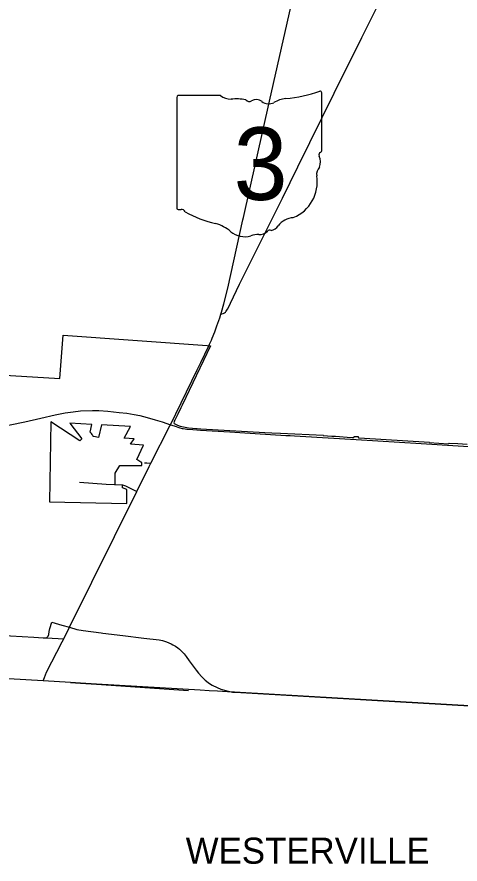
# Model space of a CAD drawing. Extents: x 1729596 to 1925846, y 659247 to 911751.
# Drawn here: x 1847054 to 1855559, y 773819 to 790063 of the extents above; entities that cross this region are included whole.
import ezdxf

# ---------------------------------------------------------------- set-up
doc = ezdxf.new("R2010")
doc.units = 0
for name, color, linetype in [('GM_X_City_Street', 7, 'Continuous'), ('GM_X_Corporation', 7, 'Continuous'), ('GM_X_Corporation_Text', 7, 'Continuous'), ('GM_X_County', 7, 'Continuous'), ('GM_X_County_Road', 7, 'Continuous'), ('GM_X_State_Route', 7, 'Continuous'), ('GM_X_State_Shield', 7, 'Continuous'), ('GM_X_Township_Road', 7, 'Continuous')]:
    doc.layers.add(name, color=color, linetype=linetype)

msp = doc.modelspace()

# ---------------------------------------------------------------- linework, layer by layer
at = {"layer": 'GM_X_City_Street'}
for points in [[(1845750, 781984), (1846636, 782185), (1847206, 782302), (1847513, 782368), (1847786, 782434), (1847977, 782469), (1848131, 782490), (1848273, 782507), (1848502, 782514), (1848624, 782515), (1848801, 782501), (1849017, 782481), (1849162, 782462), (1849304, 782438), (1849411, 782418), (1849555, 782383), (1849710, 782340), (1849838, 782298), (1850003, 782242)], [(1850003, 782242), (1850074, 782221), (1850183, 782185), (1850228, 782173), (1850245, 782170), (1850281, 782163), (1850312, 782159), (1850325, 782158), (1850431, 782150), (1850574, 782141), (1851143, 782107), (1851335, 782095)], [(1851335, 782095), (1852214, 782040)], [(1852214, 782040), (1852297, 782035), (1852381, 782031), (1852490, 782023), (1853564, 781958), (1854813, 781882), (1856233, 781796), (1856759, 781767), (1857122, 781742)], [(1849499, 781514), (1849547, 781511), (1849624, 781505)], [(1849078, 781088), (1849139, 781069), (1849352, 780964)], [(1846702, 778207), (1847381, 778168), (1847556, 778157), (1847623, 778159), (1847653, 778187), (1847668, 778222), (1847673, 778281), (1847683, 778338), (1847722, 778457)], [(1847722, 778457), (1847915, 778403), (1848062, 778361)], [(1848062, 778361), (1848204, 778314), (1848323, 778297), (1848668, 778252), (1848705, 778248)], [(1848705, 778248), (1849085, 778201), (1849491, 778152), (1849783, 778117), (1849847, 778104), (1849922, 778081), (1850012, 778044), (1850046, 778026), (1850094, 777998), (1850140, 777966), (1850171, 777942), (1850219, 777897), (1850262, 777849), (1850300, 777796), (1850362, 777718), (1850435, 777616), (1850491, 777539), (1850536, 777481), (1850600, 777410), (1850669, 777346), (1850724, 777300), (1850767, 777270), (1850802, 777249), (1850896, 777202), (1850967, 777174), (1851065, 777144), (1851193, 777116), (1851228, 777114), (1851242, 777113)], [(1847623, 778159), (1847953, 778140)], [(1848085, 777300), (1848276, 777289), (1848580, 777271), (1850345, 777150)], [(1851242, 777113), (1853977, 776957), (1854746, 776908), (1855849, 776844), (1860837, 776510)]]:
    msp.add_lwpolyline(points, dxfattribs=at)
at = {"layer": 'GM_X_Corporation'}
msp.add_lwpolyline([(1845556, 783268), (1847880, 783128), (1847941, 783961), (1850704, 783760), (1850771, 783756), (1850223, 782617), (1850199, 782567), (1850139, 782444), (1850095, 782354), (1850085, 782333), (1850074, 782313), (1850069, 782299), (1850068, 782279), (1850071, 782269), (1850095, 782252), (1850134, 782235), (1850187, 782215), (1850218, 782207), (1850250, 782200), (1850345, 782187), (1850498, 782169), (1850510, 782168), (1850585, 782164), (1851810, 782096), (1851944, 782088), (1852113, 782080), (1852935, 782042), (1852934, 782037), (1853098, 782027), (1853168, 782023), (1853247, 782018), (1853247, 782016), (1853395, 782006), (1853479, 782000), (1853492, 781999), (1853509, 781998), (1853511, 781998), (1853514, 781999), (1853517, 782000), (1853519, 782001), (1853521, 782002), (1853522, 782003), (1853524, 782005), (1853526, 782007), (1853527, 782010), (1853528, 782013), (1853529, 782016), (1853529, 782020), (1853603, 782018), (1853603, 782011), (1853603, 782008), (1853604, 782004), (1853605, 782001), (1853607, 781999), (1853608, 781997), (1853610, 781995), (1853614, 781993), (1853615, 781992), (1853618, 781992), (1853621, 781991), (1854969, 781911), (1854968, 781901), (1855339, 781880), (1855340, 781890), (1855349, 781890), (1855515, 781881), (1855693, 781873)], dxfattribs=at)
msp.add_lwpolyline([(1847680, 780763), (1849165, 780736), (1849163, 781002), (1849082, 781034), (1849083, 781084), (1848937, 781088), (1848942, 781314), (1849029, 781462), (1849454, 781459), (1849454, 781517), (1849430, 781526), (1849356, 781577), (1849486, 781850), (1849232, 781869), (1849306, 781970), (1849115, 781988), (1849235, 782207), (1848677, 782244), (1848617, 782001), (1848528, 782020), (1848519, 782020), (1848515, 782021), (1848510, 782031), (1848500, 782057), (1848482, 782077), (1848469, 782087), (1848458, 782099), (1848494, 782247), (1848066, 782273), (1848300, 781976), (1848262, 781937), (1847707, 782296)], close=True, dxfattribs=at)
at = {"layer": 'GM_X_County'}
msp.add_lwpolyline([(1855849, 776844), (1854746, 776908), (1853977, 776957), (1851228, 777114), (1851193, 777116), (1850903, 777132), (1850744, 777141), (1850569, 777151), (1848580, 777271), (1848276, 777289), (1848085, 777300), (1847560, 777333), (1845449, 777453), (1843361, 777564), (1842358, 777614), (1840924, 777694), (1840611, 777712), (1840257, 777736), (1837085, 777931), (1837011, 777935), (1836973, 777937), (1836651, 777955), (1835956, 777979)], dxfattribs=at)
at = {"layer": 'GM_X_County_Road'}
for points in [[(1851209, 784694), (1851326, 784936), (1852148, 786590), (1852443, 787187), (1853141, 788601), (1853675, 789667), (1853798, 789914), (1853979, 790280), (1854272, 790859), (1854392, 791103), (1854649, 791581), (1855260, 792799), (1855898, 794041), (1856273, 794777), (1856673, 795566), (1856869, 795971), (1857028, 796294)], [(1850968, 784364), (1851009, 784379), (1851023, 784383), (1851040, 784392), (1851054, 784403), (1851062, 784412), (1851069, 784422), (1851092, 784460), (1851118, 784507), (1851150, 784573), (1851209, 784694)]]:
    msp.add_lwpolyline(points, dxfattribs=at)
at = {"layer": 'GM_X_State_Route'}
for points in [[(1851027, 784561), (1851027, 784562), (1851101, 784861), (1851390, 786171), (1851399, 786214), (1851899, 788445), (1852470, 790966), (1852613, 791609), (1852746, 792202), (1852871, 792760), (1853072, 793659), (1853214, 794287), (1853225, 794338)], [(1850785, 783867), (1850801, 783904), (1850850, 784024), (1850893, 784139), (1850946, 784292), (1850968, 784364), (1850980, 784401), (1851027, 784561)], [(1850584, 783434), (1850737, 783758), (1850741, 783767), (1850750, 783788), (1850785, 783867)], [(1850003, 782242), (1850516, 783296), (1850578, 783422), (1850584, 783434)], [(1849593, 781442), (1849619, 781493), (1849624, 781505), (1849991, 782220), (1850003, 782242)], [(1847923, 778082), (1847953, 778140), (1848062, 778361), (1849352, 780964), (1849593, 781442)], [(1847560, 777333), (1847581, 777396), (1847623, 777500), (1847923, 778082)]]:
    msp.add_lwpolyline(points, dxfattribs=at)
at = {"layer": 'GM_X_State_Shield'}
for p, q in [((1850120, 788518), (1850120, 786405)), ((1850120, 788518), (1850120, 786405)), ((1850963, 788554), (1850147, 788554)), ((1850963, 788554), (1850147, 788554)), ((1852904, 787501), (1852904, 788607)), ((1852904, 787501), (1852904, 788607)), ((1852904, 787501), (1852904, 787501)), ((1852904, 787501), (1852904, 787501))]:
    msp.add_line(p, q, dxfattribs=at)
for centre, radius, start, end in [((1851913, 791435), 2953, 275.8445, 288.9065), ((1851913, 791435), 2953, 275.8445, 288.9065), ((1852873, 788611), 31, 351.8621, 97.738), ((1852873, 788611), 31, 351.8621, 97.738), ((1850152, 788522), 32.3, 98.1301, 188.1301), ((1850152, 788522), 32.3, 98.1301, 188.1301), ((1851157, 788800), 313, 231.6195, 271.1119), ((1851157, 788800), 313, 231.6195, 271.1119), ((1851261, 787368), 1123, 80.4867, 94.9883), ((1851261, 787368), 1123, 80.4867, 94.9883), ((1852289, 787909), 594, 97.3462, 120.7689), ((1852289, 787909), 594, 97.3462, 120.7689), ((1851516, 788533), 90.3, 219.7921, 297.1024), ((1851516, 788533), 90.3, 219.7921, 297.1024), ((1851648, 788289), 188, 54.4667, 119.1411), ((1851648, 788289), 188, 54.4667, 119.1411), ((1851890, 788624), 226, 233.8562, 294.8282), ((1851890, 788624), 226, 233.8562, 294.8282), ((1852897, 787420), 48, 107.944, 210.337), ((1852897, 787420), 48, 107.944, 210.337), ((1852592, 787280), 288, 340.033, 23.6496), ((1852592, 787280), 288, 340.033, 23.6496), ((1852871, 787497), 33.2, 289.6038, 7.7341), ((1852871, 787497), 33.2, 289.6038, 7.7341), ((1853015, 787039), 210, 136.8065, 186.9296), ((1853015, 787039), 210, 136.8065, 186.9296), ((1852078, 786898), 739, 292.3089, 8.9858), ((1852078, 786898), 739, 292.3089, 8.9858), ((1850152, 786400), 32.5, 171.9584, 258.3066), ((1850152, 786400), 32.5, 171.9584, 258.3066), ((1850157, 786616), 248, 267.339, 280.6039), ((1850157, 786616), 248, 267.339, 280.6039), ((1850208, 786283), 89.5, 29.7484, 93.2717), ((1850208, 786283), 89.5, 29.7484, 93.2717), ((1851338, 788181), 2132, 240.4129, 257.1985), ((1851338, 788181), 2132, 240.4129, 257.1985), ((1852389, 785811), 404, 94.4031, 142.5768), ((1852389, 785811), 404, 94.4031, 142.5768), ((1850703, 785455), 667, 47.1842, 75.836), ((1850703, 785455), 667, 47.1842, 75.836), ((1851877, 786200), 239, 282.8732, 323.2771), ((1851877, 786200), 239, 282.8732, 323.2771), ((1851424, 786272), 423, 230.7004, 286.2918), ((1851424, 786272), 423, 230.7004, 286.2918), ((1851669, 785542), 348, 85.6951, 111.2099), ((1851669, 785542), 348, 85.6951, 111.2099), ((1851700, 786114), 226, 268.777, 315.5493), ((1851700, 786114), 226, 268.777, 315.5493), ((1851904, 785909), 63.5, 65.7517, 132.6484), ((1851904, 785909), 63.5, 65.7517, 132.6484)]:
    msp.add_arc(centre, radius, start, end, dxfattribs=at)
at = {"layer": 'GM_X_Township_Road'}
msp.add_lwpolyline([(1848256, 781141), (1848764, 781105), (1849078, 781088)], dxfattribs=at)

# ---------------------------------------------------------------- texts
at = {"layer": 'GM_X_Corporation_Text'}
msp.add_text('WESTERVILLE', height=500, rotation=0, dxfattribs=at).set_placement((1850293, 773826))
at = {"layer": 'GM_X_State_Shield'}
msp.add_text('3', height=1392, dxfattribs=at).set_placement((1851212, 786554))
msp.add_text('3', height=1392, dxfattribs=at).set_placement((1851212, 786554))

doc.saveas('drawing.dxf')
